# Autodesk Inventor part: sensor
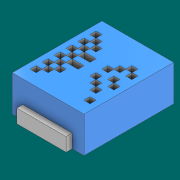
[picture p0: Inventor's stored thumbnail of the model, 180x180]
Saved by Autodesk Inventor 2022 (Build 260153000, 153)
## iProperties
Created: 2021-11
Part Number: sensor
Material: Generic
Document SubType Name: Modeling
Designer: santi
Density: 1 g/cm^3
Appearance: Default
Author: santi
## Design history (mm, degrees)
sketch "Sketch1"
  geometry: L1 (0, 0)-(0, -15); L2 (0, -15)-(12, -15); L3 (12, -15)-(12, 0); L4 (12, 0)-(0, 0)
  constraints: 8 end point, 3 perpendicular, 1 vertical
  dimensions: "d0" = 15 distance of L1.start L1.end; "d1" = 12 distance of L1.end L2.end
extrude "Extrusion1" new body sketch "Sketch1" distance "d2" = 6; taper "d3" = 0 deg
sketch "Sketch2"
  geometry: L1 (0, 15)-(-12, 15) reference; L2 (-12, 15)-(-12, 0) reference; L3 (-12, 0)-(0, 0) reference; L4 (0, 0)-(0, 15) reference; L5 (-11, 14)-(-1, 14); L6 (-1, 14)-(-1, 1); L7 (-1, 1)-(-11, 1); L8 (-11, 1)-(-11, 14); L9 (-2, 13)-(-10, 13); L10 (-10, 13)-(-10, 2); L11 (-10, 2)-(-2, 2); L12 (-2, 2)-(-2, 13); L13 (-9, 12)-(-3, 12); L14 (-3, 12)-(-3, 3); L15 (-3, 3)-(-9, 3); L16 (-9, 3)-(-9, 12); L17 (-4, 11)-(-8, 11); L18 (-8, 11)-(-8, 4); L19 (-8, 4)-(-4, 4); L20 (-4, 4)-(-4, 11); L21 (-7, 10)-(-5, 10); L22 (-5, 10)-(-5, 5); L23 (-5, 5)-(-7, 5); L24 (-7, 5)-(-7, 10); L25 (-5.5, 5.5)-(-5.5, 9.5); L26 (-5.5, 9.5)-(-6.5, 9.5); L27 (-6.5, 9.5)-(-6.5, 5.5); L28 (-6.5, 5.5)-(-5.5, 5.5); L29 (0, 15)-(-12, 15) reference; L30 (-12, 15)-(0, 15); L31 (0, 14)-(-12, 14); L32 (0, 13)-(-12, 13); L33 (0, 12)-(-12, 12); L34 (0, 11)-(-12, 11); L35 (0, 10)-(-12, 10); L36 (0, 9)-(-12, 9); L37 (0, 8)-(-12, 8); L38 (0, 7)-(-12, 7); L39 (0, 6)-(-12, 6); L40 (0, 5)-(-12, 5); L41 (0, 4)-(-12, 4); L42 (0, 3)-(-12, 3); L43 (0, 2)-(-12, 2); L44 (0, 1)-(-12, 1); 77 further points
  constraints: 78 end point, 15 equal length, 18 other
  dimensions: "d4" = 1 distance between parallel lines of L1 L5; "d5" = 1 distance between parallel lines of L5 L9; "d6" = 1 distance between parallel lines of L9 L13; "d7" = 1 distance between parallel lines of L13 L17; "d8" = 1 distance between parallel lines of L17 L21; "d9" = 0.5 distance between parallel lines of L22 L25; "d10" = 1 distance between parallel lines of L1 L31; "d11" = 1 distance between parallel lines of L31 L32; "d12" = 1 distance between parallel lines of L32 L33; "d13" = 1 distance between parallel lines of L33 L34; "d14" = 1 distance between parallel lines of L34 L35; "d15" = 1 distance between parallel lines of L35 L36; "d16" = 1 distance between parallel lines of L36 L37; "d17" = 1 distance between parallel lines of L37 L38; "d18" = 1 distance between parallel lines of L38 L39; "d19" = 1 distance between parallel lines of L39 L40; "d20" = 1 distance between parallel lines of L40 L41; "d21" = 1 distance between parallel lines of L41 L42; "d22" = 1 distance between parallel lines of L42 L43; "d23" = 1 distance between parallel lines of L43 L44
extrude "Extrusion2" cut sketch "Sketch2" distance "d24" = 2; taper "d25" = 0 deg
sketch "Sketch3"
  geometry: L1 (0, 0)-(12, 0) reference; L2 (1.783, 0)-(10.012, 0); L3 (10.012, 0)-(10.012, 2.274); L4 (10.012, 2.274)-(1.783, 2.274); L5 (1.783, 2.274)-(1.783, 0); 1 further point
  constraints: 8 end point, 2 parallel, 1 horizontal, 1 perpendicular, 1 point on line
extrude "Extrusion3" join sketch "Sketch3" distance "d26" = 1; taper "d27" = 0 deg
body "Solid1"
node "Projected Loop1"
